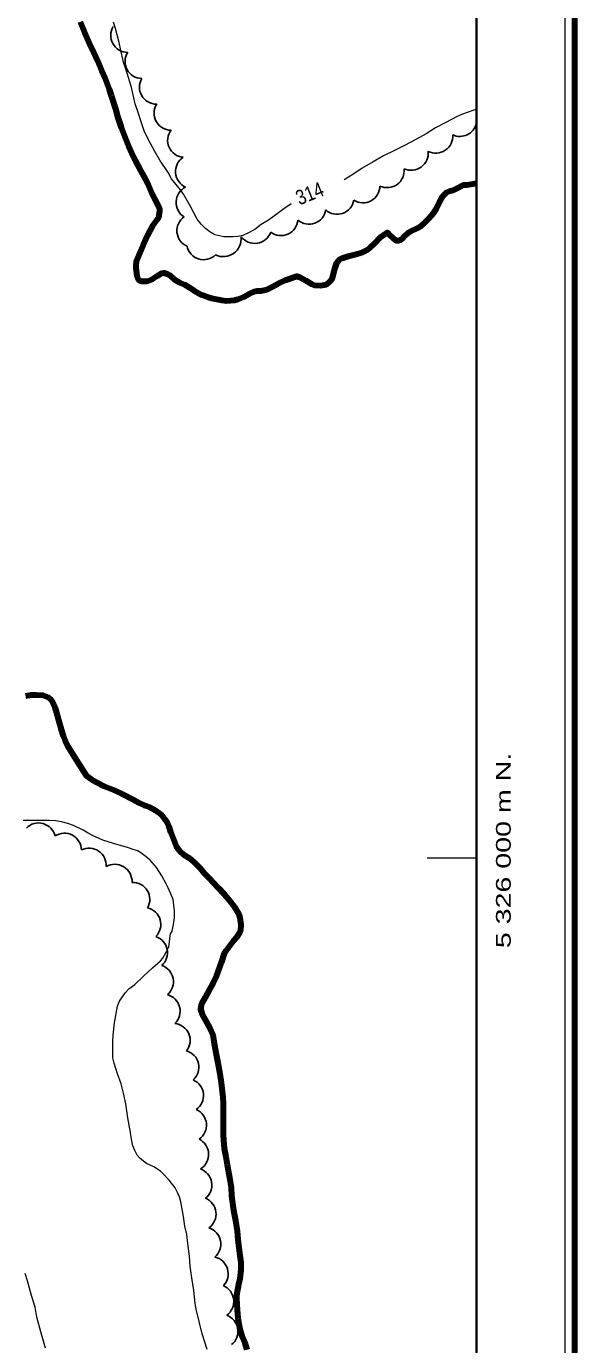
# Model space of a CAD drawing. Extents: x 240591 to 242335, y 5323482 to 5326937.
# Drawn here: x 242210.1 to 242321.7, y 5325901 to 5326169.4 of the extents above; entities that cross this region are included whole.
import ezdxf
from ezdxf.enums import TextEntityAlignment as Align

# ---------------------------------------------------------------- set-up
doc = ezdxf.new("R2010")
doc.units = 0
doc.header["$LTSCALE"] = 1.2
doc.linetypes.add('DASH_DOUBLE_DOT', pattern=[9.2, 5, -1.2, 0.3, -1.2, 0.3, -1.2])
doc.linetypes.add('LONG_DASHED', pattern=[7.5, 6, -1.5])
for name, color, linetype, lineweight in [('2', 7, 'Continuous', 13), ('4', 7, 'DASH_DOUBLE_DOT', 53), ('44', 7, 'Continuous', 25), ('60', 7, 'Continuous', 35), ('61', 7, 'Continuous', 13)]:
    doc.layers.add(name, color=color, linetype=linetype, lineweight=lineweight)

msp = doc.modelspace()

# ---------------------------------------------------------------- linework, layer by layer
at = {"layer": '2'}
for points in [[(242241.5, 5326136.1), (242239.7, 5326138.3), (242239, 5326139.6), (242237.3, 5326142.1), (242236.3, 5326143.9), (242234.9, 5326146.4), (242234.1, 5326148.1), (242233.5, 5326149.9), (242232.9, 5326151.8), (242232.3, 5326153.6), (242231.5, 5326156.9), (242230.7, 5326159.6), (242229.9, 5326162.1), (242229.3, 5326164.8), (242229, 5326166.1), (242228.3, 5326168.9), (242227.9, 5326170.2)], [(242239.1, 5325982), (242239.5, 5325984.6), (242239.8, 5325985.2), (242240.1, 5325986.5), (242240.3, 5325987.9), (242240.3, 5325989.3), (242240, 5325991.6), (242239.7, 5325992.4), (242239, 5325994), (242238.6, 5325994.8), (242237.7, 5325996.4), (242236.6, 5325998.1), (242235.3, 5325999.6), (242234.5, 5326000.3), (242233.7, 5326000.9), (242232.8, 5326001.5), (242231.9, 5326001.8), (242230.9, 5326002.1), (242227.9, 5326003), (242225.7, 5326003.7), (242223.7, 5326004.6), (242222.7, 5326005.1), (242221.7, 5326005.7), (242219.7, 5326006.7), (242218.6, 5326007.1), (242217.3, 5326007.4), (242216.1, 5326007.6), (242214.8, 5326007.7), (242212.2, 5326007.7), (242209.5, 5326007.7)]]:
    msp.add_lwpolyline(points, dxfattribs=at)
at = {"layer": '2', "linetype": 'LONG_DASHED'}
for points in [[(242301.7, 5326152.5), (242301.2, 5326152.3), (242298.9, 5326151.5), (242297.8, 5326151), (242295.5, 5326149.8), (242293.4, 5326148.7), (242291.5, 5326147.5), (242289.4, 5326146.3), (242287.1, 5326145.1), (242284.9, 5326144), (242282.8, 5326143), (242280.7, 5326141.8), (242278.5, 5326140.5), (242276.6, 5326139.2), (242274.8, 5326138.1)], [(242264, 5326133.2), (242262.5, 5326132.2), (242260.9, 5326131), (242259.4, 5326129.9), (242257.9, 5326129), (242256.6, 5326128), (242255.1, 5326127.2), (242254.2, 5326126.8), (242253.2, 5326126.6), (242252.2, 5326126.5), (242250.3, 5326126.5), (242248.5, 5326126.9), (242247.5, 5326127.5), (242246.6, 5326128.2), (242245.7, 5326129.1), (242244.9, 5326130.1), (242244.2, 5326131.4), (242243.5, 5326132.8), (242242.1, 5326135.2), (242241.5, 5326136.1)], [(242246.9, 5325900), (242245.9, 5325903.2), (242245.3, 5325905.7), (242244.7, 5325908.2), (242244.5, 5325909.4), (242244.2, 5325912), (242243.8, 5325914.6), (242243.5, 5325917), (242243.3, 5325919), (242243, 5325921.6), (242242.8, 5325923.4), (242242.4, 5325925.1), (242242.1, 5325927.1), (242241.6, 5325930.1), (242241.3, 5325931.1), (242240.9, 5325932), (242240.4, 5325932.9), (242239.2, 5325934.5), (242238, 5325935.8), (242237.4, 5325936.3), (242236.1, 5325937.2), (242234.6, 5325937.9), (242233.3, 5325938.9), (242232.7, 5325939.6), (242232.2, 5325940.5), (242231.8, 5325941.5), (242231.5, 5325942.8), (242231.3, 5325944.2), (242230.8, 5325947.2), (242230.4, 5325950), (242229.9, 5325952.2), (242229.4, 5325954.1), (242228.7, 5325956.1), (242228, 5325958.3), (242227.7, 5325959.4), (242227.7, 5325960.5), (242227.7, 5325962.8), (242227.8, 5325964), (242228.1, 5325966.5), (242228.7, 5325969.9), (242229.1, 5325970.9), (242229.7, 5325971.8), (242230.3, 5325972.7), (242231, 5325973.4), (242232.2, 5325974.3), (242234, 5325976), (242235.8, 5325977.7), (242237.4, 5325979.1), (242237.9, 5325979.7), (242238.6, 5325980.9), (242239.1, 5325982)], [(242214, 5325900.3), (242213.1, 5325903.6), (242212.3, 5325906.6), (242211.9, 5325908.6), (242211.2, 5325911), (242210.4, 5325914), (242209.9, 5325915.5)]]:
    msp.add_lwpolyline(points, dxfattribs=at)
at = {"layer": '4', "linetype": 'Continuous', "lineweight": 90}
for points in [[(242221.1, 5326170.3), (242222, 5326168.1), (242223.2, 5326165.3), (242223.8, 5326164.1), (242224.7, 5326162.2), (242225.4, 5326160.4), (242226.1, 5326158.9), (242227, 5326156.5), (242227.4, 5326155.3), (242228.3, 5326152.6), (242228.7, 5326151), (242229.4, 5326148.8), (242230.1, 5326147), (242230.9, 5326145), (242231.5, 5326143.6), (242232.2, 5326142.2), (242233.4, 5326139.9), (242234.3, 5326138.3), (242234.9, 5326137.1), (242235.6, 5326135.5), (242236.3, 5326134.1), (242237.2, 5326132.3), (242237.2, 5326131.8), (242237, 5326130.4), (242236.7, 5326130), (242235.9, 5326128.9), (242235.3, 5326127.9), (242234.7, 5326126.7), (242233.9, 5326124.9), (242233.4, 5326123.7), (242232.5, 5326121.5), (242232.4, 5326120.7), (242232.4, 5326120.2), (242232.6, 5326118.5), (242232.9, 5326117.8), (242233.4, 5326117.5), (242234.2, 5326117.5), (242234.7, 5326117.5), (242235.8, 5326117.9)], [(242235.8, 5326117.9), (242236.8, 5326118.6), (242237.7, 5326119.1), (242238.2, 5326119.2), (242238.8, 5326119), (242239.3, 5326118.7), (242240.3, 5326117.8), (242241.3, 5326117.2), (242242.3, 5326116.8), (242243.3, 5326116.2), (242244.2, 5326115.6), (242245.8, 5326114.7), (242247.1, 5326114.2), (242247.8, 5326114), (242249.9, 5326113.6), (242250.8, 5326113.5), (242252.5, 5326113.6), (242253.2, 5326113.8), (242254.4, 5326114.3), (242255.5, 5326114.9), (242256.5, 5326115.4), (242257.1, 5326115.5), (242257.9, 5326115.5), (242259.1, 5326115.8), (242260.3, 5326116.4), (242261.5, 5326117.1), (242262.8, 5326117.7), (242265.2, 5326118.5), (242265.8, 5326118.3), (242267, 5326117.6), (242268.2, 5326116.9), (242268.8, 5326116.7), (242270, 5326116.6), (242271.2, 5326116.8), (242271.7, 5326117.2), (242272.1, 5326117.6), (242272.4, 5326118.1), (242272.6, 5326118.7), (242272.9, 5326120), (242273.3, 5326121.2), (242273.9, 5326122), (242274.4, 5326122.2), (242275.6, 5326122.6), (242277, 5326122.9), (242278.4, 5326123.3), (242279.5, 5326123.9), (242280, 5326124.3), (242281.1, 5326125.3), (242282.1, 5326126.4), (242283.6, 5326127.4), (242284, 5326126.9), (242285.3, 5326125.8), (242286, 5326125.8), (242286.6, 5326126.1), (242287, 5326126.6), (242287.9, 5326127.4), (242288.4, 5326127.7), (242289.5, 5326128.2), (242290.4, 5326128.7), (242291.2, 5326129.4), (242292.1, 5326130.3), (242293, 5326131.3), (242293.6, 5326132.3), (242294.2, 5326133.6), (242294.9, 5326134.8), (242295.7, 5326135.6), (242296.4, 5326135.9), (242297, 5326136), (242297.5, 5326136.3), (242299.1, 5326137.1), (242299.8, 5326137.1), (242301.4, 5326137.4), (242301.7, 5326137.4)], [(242210, 5326033.1), (242211.1, 5326033.3), (242212.1, 5326033.3), (242213.5, 5326033.2), (242214.6, 5326032.8), (242215.1, 5326032.4), (242215.4, 5326032), (242215.9, 5326030.8), (242216.1, 5326030.1), (242216.7, 5326028.1), (242217.2, 5326026.2), (242217.6, 5326024.9), (242218, 5326023.9), (242218.5, 5326022.9), (242219.5, 5326021.3), (242221, 5326018.9), (242222.4, 5326016.8), (242223.3, 5326016.1), (242224.4, 5326015.5), (242226, 5326014.7), (242227.7, 5326014), (242229.5, 5326013.2), (242232, 5326011.9), (242233.1, 5326011.3), (242234.1, 5326010.8), (242234.6, 5326010.7), (242235.1, 5326010.5), (242236.5, 5326009.7), (242237.5, 5326009), (242238.2, 5326008.1), (242238.7, 5326007.4), (242239.1, 5326006.5), (242239.5, 5326005.4), (242240, 5326004), (242240.6, 5326002.5), (242241.3, 5326001.5), (242242.2, 5326000.7), (242243.3, 5326000), (242244.2, 5325999.3), (242245.5, 5325998), (242246.3, 5325997), (242247.3, 5325996), (242249.2, 5325994), (242250.4, 5325992.7), (242251.5, 5325991.4), (242252.5, 5325990.1), (242253.4, 5325988.6), (242253.6, 5325987.9), (242253.8, 5325986.5), (242253.7, 5325985.3), (242253.5, 5325984.8), (242252.9, 5325983.9), (242252.2, 5325983.1), (242250.7, 5325981.2), (242250.4, 5325980.6), (242249.8, 5325978.7), (242248.8, 5325976.1)], [(242248.8, 5325976.1), (242248.1, 5325974.5), (242247.5, 5325973.4), (242246.5, 5325971.7), (242245.8, 5325970.4), (242245.6, 5325969.3), (242245.8, 5325968.7), (242245.9, 5325968.2), (242246.5, 5325967.1), (242247.5, 5325965.4), (242248.1, 5325964.1), (242248.3, 5325962.7), (242248.8, 5325959.7), (242249.1, 5325958.4), (242249.5, 5325956.1), (242249.8, 5325954.3), (242250.1, 5325951.4), (242250.2, 5325950.1), (242250.2, 5325948.7), (242250.2, 5325946.1), (242250.2, 5325943.6), (242250.4, 5325940.9), (242250.7, 5325939.2), (242251, 5325937.6), (242251.5, 5325935), (242251.8, 5325933), (242251.9, 5325931.3), (242252.2, 5325928.8), (242252.4, 5325927.6), (242252.7, 5325926.3), (242253, 5325924.1), (242253.2, 5325922.4), (242253.5, 5325919.6), (242253.8, 5325917.7), (242253.8, 5325916.2), (242253.6, 5325914.4), (242253.4, 5325913.6), (242252.9, 5325911.1), (242252.9, 5325910.4), (242253, 5325908.1), (242253.2, 5325906.4), (242253.6, 5325904.1), (242254, 5325902.8), (242254.5, 5325901.6), (242255, 5325900)]]:
    msp.add_lwpolyline(points, dxfattribs=at)
at = {"layer": '44'}
for centre, radius, start, end in [((242261.938, 5326130.23), 3.465, 233.34594, 355.04048), ((242250.202, 5326126.13), 3.65, 244.324, 6.29232), ((242256.595, 5326128.662), 3.492, 217.63479, 339.68642), ((242246.208, 5326125.283), 3.433, 190.98364, 314.63485), ((242236.598, 5325974.903), 3.467, 310.08019, 71.98358), ((242237.964, 5325968.894), 3.466, 313.50498, 75.53006), ((242240, 5325962.923), 3.474, 322.32643, 84.21937), ((242241.771, 5325957.467), 3.474, 311.88062, 73.6275), ((242242.707, 5325951.698), 3.47, 304.8541, 66.51063), ((242243.33, 5325945.671), 3.457, 304.72978, 66.84216), ((242243.751, 5325939.722), 3.473, 301.78338, 63.50751), ((242244.405, 5325933.504), 3.471, 308.58049, 70.21983), ((242245.269, 5325927.578), 3.465, 305.87586, 67.95228), ((242246.246, 5325921.473), 3.461, 310.20743, 72.26399), ((242247.723, 5325915.429), 3.484, 315.78724, 77.44888), ((242248.886, 5325909.801), 3.466, 305.52997, 67.35929), ((242249.725, 5325903.714), 3.471, 308.58049, 70.21983)]:
    msp.add_arc(centre, radius, start, end, dxfattribs=at)
for centre, major_axis, ratio, start_param, end_param in [((242230.756, 5326167.529), (-3.178, -1.369), 0.999602, 5.3186308, 7.4485174), ((242233.677, 5326162.209), (-3.048, -1.636), 0.999978, 5.2227082, 7.3479001), ((242236.6, 5326156.978), (-2.988, -1.742), 0.999978, 5.2174142, 7.3434075), ((242239.588, 5326151.685), (-3.03, -1.661), 0.999863, 5.2219908, 7.3503796), ((242298.362, 5326150.387), (0.931, -3.305), 0.999844, 5.5687307, 7.3556011), ((242242.337, 5326146.15), (-3.158, -1.399), 0.999995, 5.2198362, 7.3478109), ((242293.454, 5326147.002), (1.925, -2.873), 0.999451, 5.2229572, 7.344228), ((242243.978, 5326139.814), (-3.478, -0.291), 0.999866, 5.2208348, 7.3489657), ((242288.454, 5326143.515), (-0.378, 3.439), 0.999984, 2.5950106, 4.7202769), ((242283.557, 5326139.98), (1.563, -3.083), 0.999831, 5.3690745, 7.5007254), ((242244.077, 5326133.514), (-3.467, 0.175), 0.99956, 5.2181242, 7.346781), ((242278.614, 5326136.894), (0.591, -3.406), 0.999962, 5.548795, 7.6723321), ((242273.366, 5326134.564), (2.239, 2.633), 0.999995, 3.1158284, 5.2441291), ((242267.653, 5326132.535), (1.176, -3.245), 0.999555, 5.2201042, 7.3481042), ((242244.194, 5326127.753), (0.386, -3.407), 0.999938, 3.6351748, 5.7608977), ((242212.629, 5326003.72), (1.941, 2.878), 0.999962, 5.5470924, 7.6759285), ((242217.878, 5326001.63), (1.776, 2.989), 0.998334, 5.2677729, 7.3915511), ((242222.911, 5325998.611), (1.941, 2.867), 0.999453, 5.2229343, 7.3464828), ((242228.112, 5325995.244), (1.839, 3.025), 0.999953, 5.2205867, 7.3471162), ((242231.768, 5325991.628), (3.059, 1.678), 0.99815, 5.2652171, 7.386994), ((242234.019, 5325986.524), (-2.521, 2.393), 0.999995, 3.1170497, 5.2450515), ((242235.423, 5325980.8), (3.374, 0.714), 0.995344, 5.2145698, 7.3348731)]:
    msp.add_ellipse(centre, major_axis=major_axis, ratio=ratio, start_param=start_param, end_param=end_param, dxfattribs=at)
at = {"layer": '60', "lineweight": 158}
msp.add_lwpolyline([(242321.7, 5323482.5), (240590.8, 5323482.5), (240590.8, 5326907.9), (242321.7, 5326907.9)], close=True, dxfattribs=at)
at = {"layer": '60', "lineweight": 13}
msp.add_lwpolyline([(240592.8, 5323484.5), (240592.8, 5326905.9), (242319.7, 5326905.9), (242319.7, 5323484.5)], close=True, dxfattribs=at)
at = {"layer": '60'}
msp.add_lwpolyline([(240610.8, 5326369.9), (242301.7, 5326369.9), (242301.7, 5323502.5), (240610.8, 5323502.5)], close=True, dxfattribs=at)
at = {"layer": '61'}
msp.add_line((242301.7, 5326000), (242291.7, 5326000), dxfattribs=at)

# ---------------------------------------------------------------- texts
at = {"layer": '2', "width": 0.85}
msp.add_text('314', height=3, rotation=21.921, dxfattribs=at).set_placement((242265.7, 5326132.9))
at = {"layer": '61', "width": 1.45}
msp.add_text('5 326 000 m N.', height=3, rotation=90, dxfattribs=at).set_placement((242308.7, 5326001.6), align=Align.CENTER)

doc.saveas('drawing.dxf')
